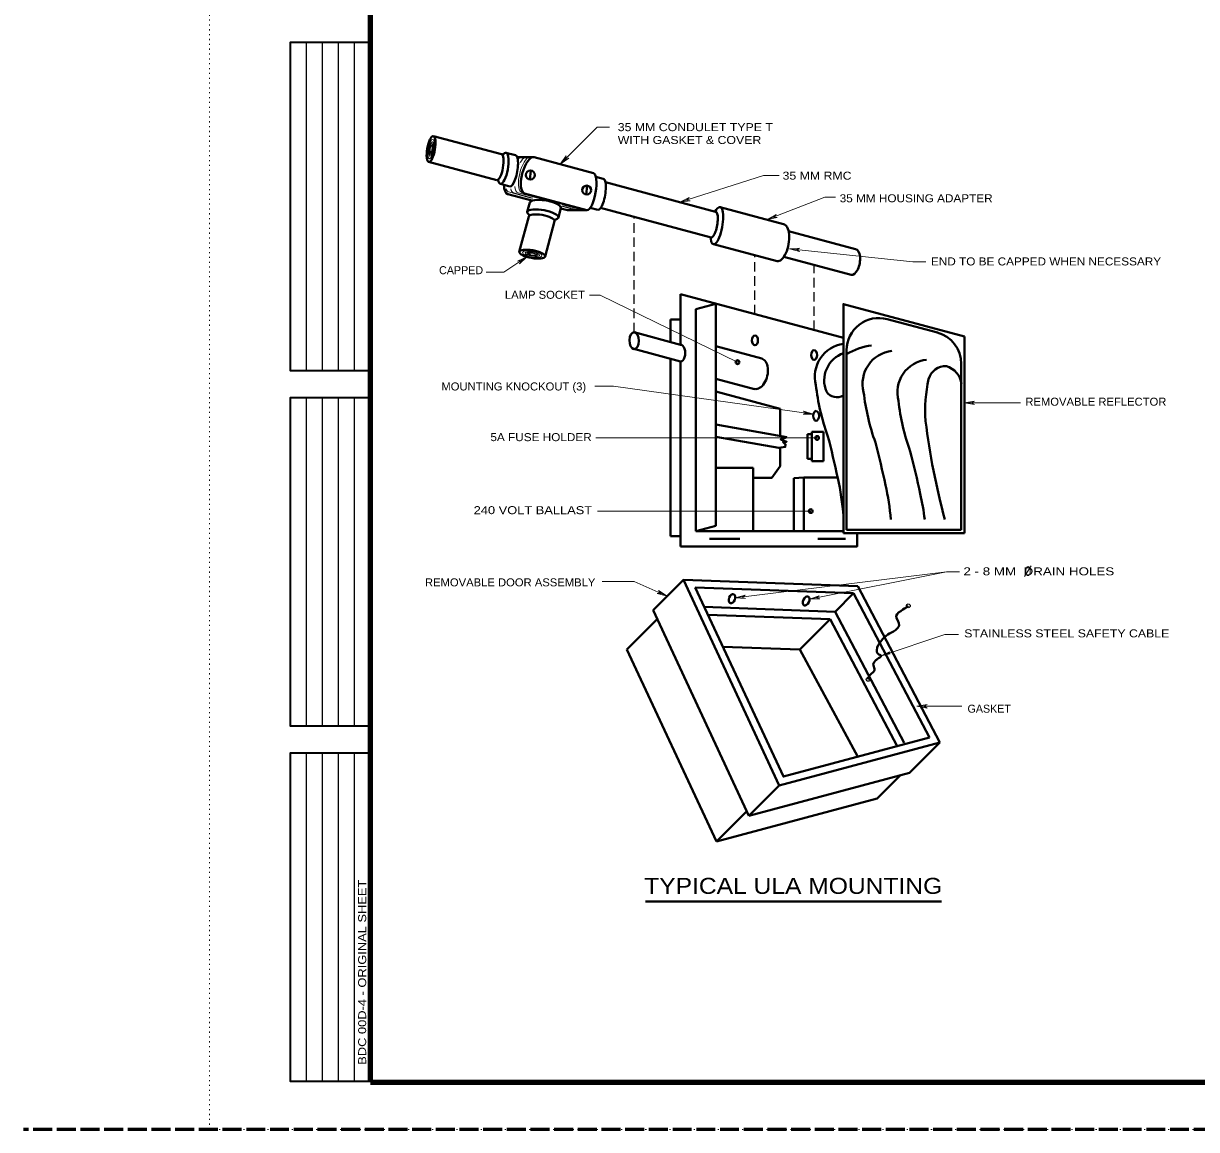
# Model space of a CAD drawing. Extents: x 312583 to 312854, y 144419 to 144597.
# Drawn here: x 312583.5 to 312695, y 144418.6 to 144523.7 of the extents above; entities that cross this region are included whole.
import ezdxf
from ezdxf.enums import TextEntityAlignment as Align

# ---------------------------------------------------------------- set-up
doc = ezdxf.new("R2010")
doc.units = 0
doc.header["$LTSCALE"] = 0.3
for name, pattern in [('DOTTED', [1.5, 0.3, -1.2]), ('LONG_DASHED', [7.5, 6, -1.5]), ('MEDIUM_DASHED', [4.5, 3, -1.5])]:
    doc.linetypes.add(name, pattern=pattern)
for name, color, linetype, lineweight in [('1', 7, 'Continuous', 40), ('2', 7, 'Continuous', 13), ('62', 7, 'DOTTED', 13), ('63', 7, 'LONG_DASHED', 60)]:
    doc.layers.add(name, color=color, linetype=linetype, lineweight=lineweight)

msp = doc.modelspace()

# ---------------------------------------------------------------- linework, layer by layer
at = {"layer": '1', "lineweight": 25}
for p, q in [((312610.4087, 144490.6573), (312610.4087, 144521.8756)), ((312611.9315, 144490.6573), (312611.9315, 144521.8756)), ((312613.4543, 144490.6573), (312613.4543, 144521.8756)), ((312614.9772, 144490.6573), (312614.9772, 144521.8756)), ((312610.4087, 144456.901), (312610.4087, 144488.1192)), ((312611.9315, 144456.901), (312611.9315, 144488.1192)), ((312613.4543, 144456.901), (312613.4543, 144488.1192)), ((312614.9772, 144456.901), (312614.9772, 144488.1192)), ((312610.4087, 144423.1446), (312610.4087, 144454.3629)), ((312611.9315, 144423.1446), (312611.9315, 144454.3629)), ((312613.4543, 144423.1446), (312613.4543, 144454.3629)), ((312614.9772, 144423.1446), (312614.9772, 144454.3629))]:
    msp.add_line(p, q, dxfattribs=at)
at = {"layer": '1'}
for p, q in [((312622.4642, 144512.954), (312628.9272, 144511.229)), ((312629.3565, 144511.3747), (312630.2612, 144511.137)), ((312622.0195, 144510.5083), (312628.4979, 144508.7757)), ((312630.4299, 144510.953), (312632.0322, 144510.953)), ((312632.0322, 144510.953), (312637.6672, 144509.4427)), ((312631.6335, 144508.8447), (312631.7255, 144509.6727)), ((312637.9049, 144509.0823), (312638.6025, 144508.8983)), ((312628.8429, 144508.4153), (312629.7399, 144508.1777)), ((312636.9849, 144507.4187), (312637.0769, 144508.2467)), ((312638.8095, 144508.584), (312649.2822, 144505.778)), ((312629.5252, 144507.4417), (312631.8252, 144506.8283)), ((312631.1122, 144507.5107), (312637.0462, 144505.916)), ((312631.3805, 144505.7473), (312631.6182, 144506.652)), ((312634.3399, 144505.2337), (312634.5775, 144506.1307)), ((312634.5699, 144506.0923), (312635.2215, 144505.916)), ((312635.2215, 144505.916), (312637.0462, 144505.916)), ((312637.3605, 144506.1307), (312638.0812, 144505.939)), ((312638.3572, 144506.1383), (312648.8529, 144503.3323)), ((312649.7039, 144506.215), (312655.7375, 144504.5973)), ((312630.6292, 144501.96), (312631.5262, 144505.318)), ((312633.0825, 144501.5307), (312633.9795, 144504.8887)), ((312656.2129, 144503.9227), (312662.5762, 144502.2207)), ((312649.0829, 144502.6883), (312655.1165, 144501.0707)), ((312655.7605, 144501.4847), (312662.1469, 144499.775)), ((312645.9472, 144497.9427), (312661.4185, 144493.7873)), ((312645.9472, 144493.1433), (312645.9472, 144497.9427)), ((312647.3885, 144496.509), (312649.3052, 144497.0227)), ((312649.3052, 144475.9393), (312649.3052, 144497.0227)), ((312647.3885, 144475.4257), (312647.3885, 144496.509)), ((312644.9889, 144495.5507), (312645.9472, 144495.5507)), ((312644.9889, 144493.3963), (312644.9889, 144495.5507)), ((312665.5892, 144495.566), (312670.3425, 144494.2933)), ((312641.5389, 144494.324), (312645.9472, 144493.1433)), ((312672.9185, 144475.2417), (312672.9185, 144493.9177)), ((312641.5082, 144492.737), (312645.9472, 144491.5487)), ((312649.3052, 144492.99), (312653.6599, 144491.817)), ((312661.7252, 144475.5483), (312661.7252, 144492.6067)), ((312644.9889, 144474.9427), (312644.9889, 144491.8017)), ((312645.9472, 144473.9843), (312645.9472, 144491.5487)), ((312672.6119, 144475.5483), (312672.6119, 144491.3263)), ((312649.3052, 144489.8927), (312652.9699, 144488.9113)), ((312649.3052, 144488.689), (312655.4079, 144487.056)), ((312655.4079, 144484.48), (312655.4079, 144487.056)), ((312656.0519, 144484.3727), (312649.3052, 144485.561)), ((312658.0145, 144482.3027), (312658.0145, 144484.641)), ((312658.0145, 144484.641), (312658.4285, 144484.641)), ((312658.4285, 144484.871), (312659.5325, 144484.871)), ((312658.4285, 144482.0803), (312658.4285, 144484.871)), ((312659.5325, 144482.0803), (312659.5325, 144484.871)), ((312655.2699, 144483.33), (312649.3052, 144484.3803)), ((312658.0145, 144482.3027), (312658.4285, 144482.3027)), ((312649.3052, 144481.4517), (312652.8395, 144481.4517)), ((312652.8395, 144475.4257), (312652.8395, 144481.4517)), ((312658.4285, 144482.0803), (312659.5325, 144482.0803)), ((312652.8395, 144480.501), (312654.6182, 144480.501)), ((312656.7189, 144480.4473), (312657.6542, 144480.5163)), ((312656.7189, 144475.4257), (312656.7189, 144480.4473)), ((312657.6542, 144475.4257), (312657.6542, 144480.5163)), ((312657.6542, 144480.5163), (312660.8742, 144480.5163)), ((312647.3885, 144475.4257), (312649.3052, 144475.9393)), ((312644.9889, 144474.9427), (312645.9472, 144474.9427)), ((312647.3885, 144475.4257), (312661.4185, 144475.4257)), ((312648.7072, 144474.705), (312651.5745, 144474.705)), ((312659.0035, 144474.705), (312661.6179, 144474.705)), ((312661.4185, 144475.2417), (312672.9185, 144475.2417)), ((312661.7252, 144475.5483), (312672.6119, 144475.5483)), ((312646.2155, 144470.8027), (312662.7909, 144470.1893)), ((312647.3425, 144470.082), (312662.3769, 144469.5223)), ((312670.5955, 144455.3543), (312662.7909, 144470.1893)), ((312660.6289, 144467.7743), (312662.3769, 144469.5223)), ((312669.5835, 144455.8297), (312662.3769, 144469.5223)), ((312652.4409, 144448.3777), (312643.3329, 144467.92)), ((312648.2012, 144468.2343), (312660.6289, 144467.7743)), ((312667.1839, 144455.316), (312660.6289, 144467.7743)), ((312640.8565, 144464.171), (312643.7392, 144467.0537)), ((312648.5539, 144467.483), (312660.1689, 144467.0537)), ((312666.5322, 144455.0093), (312660.1689, 144467.0537)), ((312649.9722, 144464.447), (312657.2862, 144464.171)), ((312649.3589, 144445.932), (312640.8565, 144464.171)), ((312664.6309, 144450.026), (312666.8465, 144452.2417)), ((312652.4409, 144448.3777), (312655.3235, 144451.2603)), ((312649.3589, 144445.932), (312664.6309, 144450.026)), ((312649.3589, 144445.932), (312652.2415, 144448.8147))]:
    msp.add_line(p, q, dxfattribs=at)
at = {"layer": '1', "lineweight": 13}
for p, q in [((312629.6172, 144507.6487), (312631.7715, 144507.066)), ((312630.1002, 144507.5643), (312631.9172, 144507.0737)), ((312630.5219, 144507.5643), (312632.3849, 144507.066)), ((312634.6235, 144506.307), (312635.5512, 144506.054)), ((312634.7155, 144506.4373), (312636.4559, 144505.9697)), ((312634.7692, 144506.307), (312636.0342, 144505.9697))]:
    msp.add_line(p, q, dxfattribs=at)
at = {"layer": '1', "linetype": 'MEDIUM_DASHED', "lineweight": 25}
for p, q in [((312641.5389, 144494.324), (312641.5389, 144505.2873)), ((312653.0159, 144496.0413), (312653.0159, 144501.638)), ((312658.6355, 144494.531), (312658.6355, 144500.718))]:
    msp.add_line(p, q, dxfattribs=at)
at = {"layer": '1', "lineweight": 158}
msp.add_line((312616.5, 144423.0846), (312849, 144423.0846), dxfattribs=at)
msp.add_lwpolyline([(312616.5, 144423.1446), (312616.5, 144585.0846), (312849, 144585.0846)], dxfattribs=at)
at = {"layer": '1', "lineweight": 35}
for points in [[(312616.5, 144490.6573), (312608.8858, 144490.6573), (312608.8858, 144521.8756), (312616.5, 144521.8756)], [(312616.5, 144456.901), (312608.8858, 144456.901), (312608.8858, 144488.1192), (312616.5, 144488.1192)], [(312616.5, 144423.1446), (312608.8858, 144423.1446), (312608.8858, 144454.3629), (312616.5, 144454.3629)]]:
    msp.add_lwpolyline(points, dxfattribs=at)
at = {"layer": '1'}
for points in [[(312661.4185, 144475.2417), (312661.4185, 144496.9997), (312672.9185, 144493.9177)], [(312656.0519, 144484.3727), (312655.4692, 144484.1503), (312656.0212, 144483.9203), (312655.6915, 144483.8897), (312655.9215, 144483.6673), (312655.8909, 144483.4373), (312655.2699, 144483.33)], [(312654.6182, 144480.501), (312655.4079, 144481.5973), (312655.4079, 144483.2993)], [(312645.9472, 144473.9843), (312662.7219, 144473.9843), (312662.7219, 144475.2417)], [(312643.3329, 144467.92), (312646.2155, 144470.8027), (312655.3235, 144451.2603), (312670.5955, 144455.3543)], [(312647.3425, 144470.082), (312655.7222, 144452.1113), (312669.5835, 144455.8297)], [(312662.7755, 144454.005), (312657.2862, 144464.171), (312660.1689, 144467.0537)], [(312652.4409, 144448.3777), (312667.7129, 144452.4717), (312670.5955, 144455.3543)]]:
    msp.add_lwpolyline(points, dxfattribs=at)
for centre in [(312631.6795, 144509.2587), (312637.0309, 144507.8327)]:
    msp.add_circle(centre, 0.4165, dxfattribs=at)
for centre, radius, start, end in [((312664.7919, 144492.6068), 3.0667, 74.97172, 180), ((312669.5452, 144491.33), 3.0667, 0, 74.98756), ((312661.8369, 144490.1061), 3.1355, 97.66868, 194.70824), ((312662.3629, 144489.7393), 2.7682, 109.94716, 202.29149), ((312664.8558, 144487.1463), 5.9762, 97.24774, 121.59002), ((312666.3756, 144489.4391), 3.1355, 96.45684, 194.70824), ((312669.6799, 144488.6034), 3.1355, 96.45684, 194.70824), ((312671.1213, 144489.4425), 1.6634, 87.24823, 164.81432), ((312670.6442, 144489.1756), 2.0072, 7.35773, 73.88813), ((312679.6064, 144491.6314), 20.9313, 186.36762, 199.88885), ((312682.639, 144486.9345), 13.4504, 167.3619, 184.43917), ((312660.8046, 144489.338), 1.1953, 212.88625, 300.90272), ((312684.1451, 144490.9644), 20.9313, 186.36762, 199.88885), ((312687.4494, 144490.1288), 20.9313, 186.36762, 199.88885), ((312737.6635, 144494.4313), 68.9697, 187.11618, 195.04114), ((312579.808, 144463.3416), 82.8651, 11.93481, 14.80109), ((312584.3467, 144462.6746), 82.8651, 11.93481, 14.80109), ((312587.651, 144461.8389), 82.8651, 11.93481, 14.80109), ((312638.0571, 144475.25), 23.4159, 3.90719, 12.90112), ((312642.5892, 144474.5823), 23.4159, 4.795, 12.90233), ((312645.8935, 144473.7467), 23.4159, 6.84619, 12.89723)]:
    msp.add_arc(centre, radius, start, end, dxfattribs=at)
for centre, major_axis, ratio, start_param, end_param in [((312622.2485, 144511.7309), (0.2157, 1.2231), 0.296319, 0.02053438, 6.28318531), ((312628.7115, 144510.0059), (0.2157, 1.2231), 0.296319, 3.14669052, 6.28318531), ((312629.0956, 144509.8968), (0.261, 1.48), 0.296319, 2.43548019, 6.92644613), ((312630.0003, 144509.6592), (0.261, 1.48), 0.296319, 3.14159265, 6.28318531), ((312631.5722, 144509.2318), (0.46, 1.7212), 0.381008, 6.28318531, 9.42477796), ((312637.3539, 144507.6807), (0.3106, 1.7613), 0.296319, 3.14808295, 6.27826047), ((312629.9852, 144509.1628), (0.46, 1.7212), 0.381008, 2.17731666, 3.1415927), ((312638.3416, 144507.4205), (0.261, 1.48), 0.296319, 3.14159265, 6.28318531), ((312633.096, 144506.3911), (-1.48, 0.261), 0.296319, 3.14159265, 6.28318531), ((312632.8584, 144505.4864), (-1.48, 0.261), 0.296319, 2.43548019, 6.92644613), ((312649.3905, 144504.4531), (0.3106, 1.7613), 0.296319, 2.30013864, 7.05068871), ((312649.0665, 144504.5549), (0.2157, 1.2231), 0.296319, 3.14159265, 6.28318531), ((312632.7493, 144505.1023), (-1.2231, 0.2157), 0.296319, 3.14669052, 6.28318531), ((312655.427, 144502.834), (0.3105, 1.7633), 0.446003, 3.14159265, 6.28318531), ((312631.86, 144501.7443), (-1.2231, 0.2157), 0.296319, 0.00359552, 6.28318531), ((312662.3615, 144500.9978), (0.2147, 1.2228), 0.497926, 3.14159265, 6.28318531), ((312641.5389, 144493.5267), (0, 0.7973), 0.557692, 3.12435297, 9.3565752), ((312645.9472, 144492.346), (0, 0.7973), 0.557692, 3.14159265, 6.28318531), ((312653.3187, 144490.3795), (0.3412, 1.4375), 0.606127, 3.14159265, 6.28318531)]:
    msp.add_ellipse(centre, major_axis=major_axis, ratio=ratio, start_param=start_param, end_param=end_param, dxfattribs=at)
at = {"layer": '1', "lineweight": 13}
for centre, major_axis, ratio, start_param, end_param in [((312622.2488, 144511.73), (0.1618, 0.9173), 0.296319, 0.02053438, 6.28318531), ((312622.249, 144511.7293), (0.1213, 0.688), 0.296319, 0.02053438, 6.28318531), ((312622.2491, 144511.7288), (0.091, 0.516), 0.296319, 0.02053438, 6.28318531), ((312622.2492, 144511.7285), (0.0682, 0.387), 0.296319, 0.02053438, 6.28318531), ((312622.2493, 144511.7282), (0.0512, 0.2903), 0.296319, 0.02053438, 6.28318531), ((312631.3422, 144509.3162), (0.46, 1.7212), 0.381008, 0.43127042, 3.1415927), ((312630.5602, 144509.2855), (0.46, 1.7212), 0.381008, 0.36999894, 0.70316213), ((312630.9819, 144509.2855), (0.46, 1.7212), 0.381008, 0.36999894, 0.94197087), ((312630.0772, 144509.3698), (0.46, 1.7212), 0.381008, 2.63144314, 3.1415927), ((312630.5602, 144509.2855), (0.46, 1.7212), 0.381008, 2.55381337, 3.14159275), ((312630.9819, 144509.2855), (0.46, 1.7212), 0.381008, 2.37012299, 3.14159275), ((312631.8609, 144501.7446), (-0.9173, 0.1618), 0.296319, 0.00359552, 6.28318531), ((312631.8615, 144501.7448), (-0.688, 0.1213), 0.296319, 0.00359552, 6.28318531), ((312631.862, 144501.7449), (-0.516, 0.091), 0.296319, 0.00359552, 6.28318531), ((312631.8624, 144501.745), (-0.387, 0.0682), 0.296319, 0.00359552, 6.28318531), ((312631.8627, 144501.7451), (-0.2903, 0.0512), 0.296319, 0.00359552, 6.28318531)]:
    msp.add_ellipse(centre, major_axis=major_axis, ratio=ratio, start_param=start_param, end_param=end_param, dxfattribs=at)
at = {"layer": '1'}
for centre, major_axis in [((312653.0159, 144493.5497), (0, 0.4617)), ((312658.6355, 144492.162), (0, 0.4617)), ((312658.8272, 144486.3813), (0, 0.4617)), ((312650.8339, 144469.0159), (0.1579, 0.4339)), ((312657.8792, 144468.7958), (0.1951, 0.4185))]:
    msp.add_ellipse(centre, major_axis=major_axis, ratio=0.61101, dxfattribs=at)
msp.add_spline([(312663.7722, 144461.3497), (312663.9255, 144461.7407), (312664.1019, 144461.894), (312664.3779, 144462.3387), (312664.2552, 144462.791), (312664.4009, 144463.0593), (312664.6155, 144463.2663), (312664.9989, 144463.596), (312664.7075, 144463.78), (312664.5849, 144464.1097), (312665.0372, 144465.0373), (312665.6352, 144465.6047), (312666.3559, 144466.0263), (312666.7085, 144466.4787), (312666.4402, 144467.3757), (312667.0689, 144467.9737), (312667.5825, 144468.334)], degree=3, dxfattribs=at)
at = {"layer": '2'}
for p, q in [((312637.3069, 144497.8353), (312638.3189, 144497.8353)), ((312638.3189, 144497.8353), (312651.3599, 144491.4797)), ((312637.8129, 144489.195), (312639.5915, 144489.195)), ((312639.5915, 144489.195), (312658.5665, 144486.55)), ((312678.2469, 144487.6157), (312672.9185, 144487.6157)), ((312637.8972, 144484.2807), (312658.9192, 144484.2807)), ((312638.0659, 144477.3347), (312658.3135, 144477.3347)), ((312671.2012, 144471.577), (312651.1375, 144469.0853)), ((312671.2012, 144471.577), (312658.1985, 144468.955)), ((312672.4355, 144471.577), (312671.2012, 144471.577)), ((312678.6211, 144471.1193), (312679.2575, 144472.139)), ((312638.4875, 144470.6493), (312641.5542, 144470.6493)), ((312641.5542, 144470.6493), (312644.6669, 144469.254)), ((312671.0402, 144465.6123), (312664.9989, 144463.596)), ((312672.3589, 144465.6123), (312671.0402, 144465.6123)), ((312664.9989, 144463.596), (312665.7885, 144463.9717)), ((312664.9989, 144463.596), (312665.8575, 144463.7647)), ((312665.7885, 144463.9717), (312665.5585, 144463.78)), ((312665.8575, 144463.7647), (312665.5585, 144463.78)), ((312672.6732, 144458.789), (312668.4105, 144458.789))]:
    msp.add_line(p, q, dxfattribs=at)
at = {"layer": '2', "lineweight": 40}
msp.add_line((312642.6275, 144440.2587), (312670.7227, 144440.2587), dxfattribs=at)
at = {"layer": '2'}
for points in [[(312639.2005, 144513.805), (312638.0275, 144513.805), (312634.5239, 144510.286)], [(312655.3159, 144509.228), (312653.8439, 144509.228), (312645.8935, 144506.6827)], [(312660.6595, 144507.1427), (312659.6552, 144507.1427), (312654.1812, 144505.019)], [(312627.4782, 144500.0357), (312629.1725, 144500.0357), (312631.3499, 144501.4847)], [(312669.2615, 144501.017), (312668.0119, 144501.017), (312656.3125, 144502.259)]]:
    msp.add_lwpolyline(points, dxfattribs=at)
for points in [[(312634.5239, 144510.286), (312635.3212, 144510.8533), (312634.9762, 144510.746), (312635.0912, 144511.0833)], [(312645.8935, 144506.6827), (312646.8595, 144506.8207), (312646.5069, 144506.882), (312646.7675, 144507.1273)], [(312654.1812, 144505.019), (312655.1395, 144505.2183), (312654.7792, 144505.249), (312655.0245, 144505.5173)], [(312656.3125, 144502.259), (312657.2555, 144501.9983), (312656.9489, 144502.19), (312657.2862, 144502.3203)], [(312631.3499, 144501.4847), (312630.4605, 144501.086), (312630.8132, 144501.1243), (312630.6369, 144500.8177)], [(312658.5665, 144486.55), (312657.6312, 144486.8413), (312657.9302, 144486.642), (312657.5852, 144486.527)], [(312672.9185, 144487.6157), (312673.8845, 144487.4547), (312673.5625, 144487.6157), (312673.8845, 144487.7767)], [(312644.6669, 144469.254), (312643.8542, 144469.7983), (312644.0765, 144469.5147), (312643.7162, 144469.4993)], [(312651.1375, 144469.0853), (312652.1189, 144469.047), (312651.7739, 144469.162), (312652.0729, 144469.3613)], [(312658.1985, 144468.955), (312659.1799, 144468.9857), (312658.8272, 144469.0853), (312659.1109, 144469.3)], [(312668.4105, 144458.789), (312669.3765, 144458.628), (312669.0545, 144458.789), (312669.3765, 144458.95)]]:
    msp.add_lwpolyline(points, close=True, dxfattribs=at)
at = {"layer": '2', "lineweight": 40}
for centre in [(312651.3597, 144491.4796), (312658.919, 144484.2806), (312658.3133, 144477.3346)]:
    msp.add_circle(centre, 0.1797, dxfattribs=at)
at = {"layer": '2', "lineweight": 25}
for centre in [(312667.5823, 144468.3339), (312663.772, 144461.3496)]:
    msp.add_circle(centre, 0.1797, dxfattribs=at)
at = {"layer": '62'}
msp.add_line((312601.2, 144418.5846), (312601.2, 144596.7846), dxfattribs=at)
msp.add_lwpolyline([(312601.2, 144418.5846), (312853.5, 144418.5846), (312853.5, 144596.7846)], dxfattribs=at)
at = {"layer": '63'}
msp.add_line((312851.75, 144418.5846), (312583.526, 144418.5846), dxfattribs=at)

# ---------------------------------------------------------------- texts
at = {"layer": '1', "width": 1.2}
msp.add_text('BDC 00D-4 - ORIGINAL SHEET', height=0.7614, rotation=90, dxfattribs=at).set_placement((312616.0832, 144424.7374))
at = {"layer": '2'}
for s, width, p in [('35 MM CONDULET TYPE T', 1.15, (312639.9825, 144513.4283)), ('WITH GASKET & COVER', 1.15, (312639.9825, 144512.2083)), ('35 MM RMC', 1.15, (312655.6369, 144508.8188)), ('35 MM HOUSING ADAPTER', 1.1, (312661.0638, 144506.6698)), ('END TO BE CAPPED WHEN NECESSARY', 1.1, (312669.7358, 144500.6714)), ('LAMP SOCKET', 1.05, (312629.2625, 144497.504)), ('MOUNTING KNOCKOUT (3)', 1.05, (312623.2264, 144488.7947)), ('REMOVABLE REFLECTOR', 1.05, (312678.7013, 144487.347)), ('5A FUSE HOLDER', 1.1, (312627.8834, 144483.9799)), ('240 VOLT BALLAST', 1.2, (312626.2953, 144477.0417)), ('2 - 8 MM  DRAIN HOLES', 1.25, (312672.8189, 144471.2314)), ('REMOVABLE DOOR ASSEMBLY', 1.05, (312621.6672, 144470.1831)), ('STAINLESS STEEL SAFETY CABLE', 1.15, (312672.8955, 144465.337))]:
    msp.add_text(s, height=0.76, dxfattribs=dict(at, width=width)).set_placement(p)
for s, p in [('CAPPED', (312623.0102, 144499.8382)), ('GASKET', (312673.2099, 144458.1823))]:
    msp.add_text(s, height=0.76, dxfattribs=at).set_placement(p)
for s, height, width, p in [('0', 0.92, 0.85, (312678.9585, 144471.173)), ('TYPICAL ULA MOUNTING', 1.52, 1.15, (312656.6518, 144440.9724))]:
    msp.add_text(s, height=height, dxfattribs=dict(at, width=width)).set_placement(p, align=Align.CENTER)

doc.saveas('drawing.dxf')
